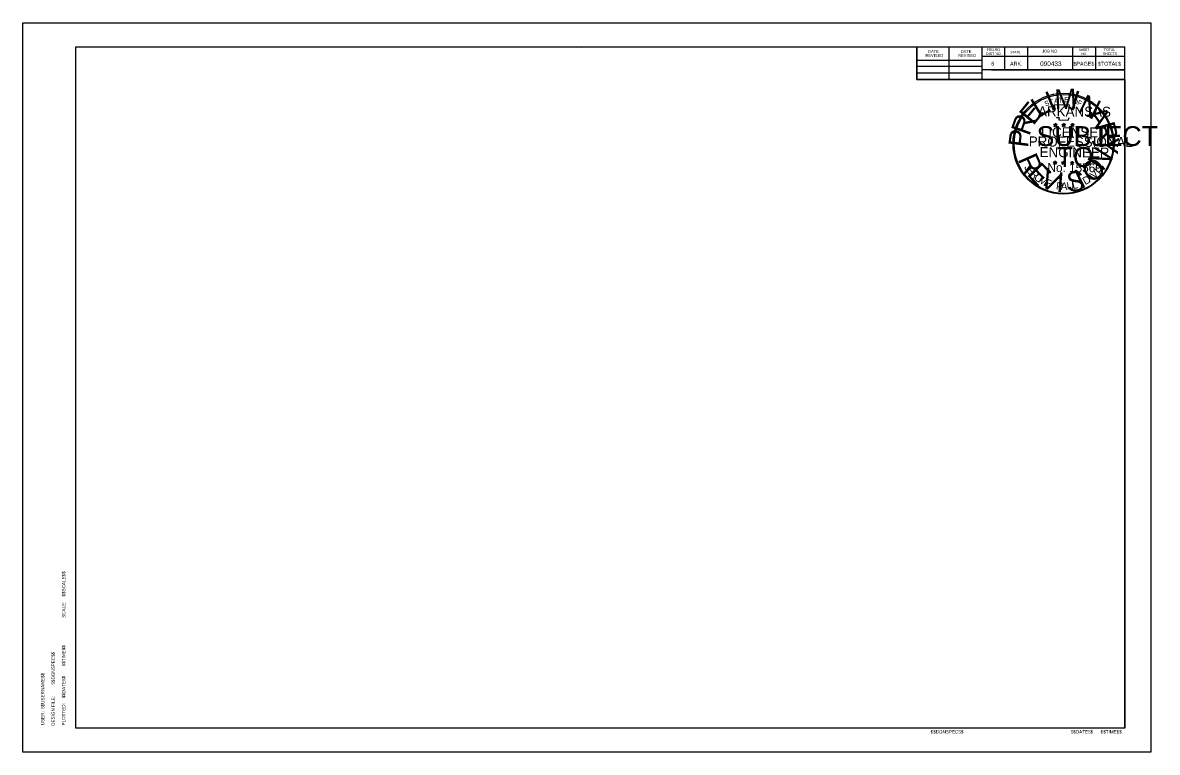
# Model space of a CAD drawing. Extents: x 0 to 34.2, y 0 to 22.
import ezdxf

# ---------------------------------------------------------------- set-up
doc = ezdxf.new("R2010")
doc.units = 0
for name, color, linetype in [('Level 1', 7, 'Continuous'), ('Level 3', 7, 'Continuous'), ('Level 38', 7, 'Continuous'), ('Level 48', 7, 'Continuous'), ('Level 49', 7, 'Continuous'), ('Level 62', 7, 'Continuous'), ('Level 63', 7, 'Continuous'), ('R_Border', 7, 'Continuous'), ('Stamp Mask', 7, 'Continuous')]:
    doc.layers.add(name, color=color, linetype=linetype)

msp = doc.modelspace()

# ---------------------------------------------------------------- linework, layer by layer
at = {"layer": 'Level 1'}
for p, q in [((1.597, 21.272), (33.215, 21.272)), ((1.597, 0.726), (1.597, 21.272)), ((26.951, 20.284), (26.951, 21.272)), ((27.919, 20.284), (27.919, 21.252)), ((28.905, 21.272), (28.905, 20.284)), ((29.589, 21.272), (29.589, 20.578)), ((30.283, 21.272), (30.283, 20.578)), ((31.641, 21.272), (31.641, 20.578)), ((32.335, 21.272), (32.335, 20.578)), ((33.215, 0.726), (33.215, 21.272)), ((26.951, 20.87), (28.905, 20.87)), ((33.215, 20.978), (28.905, 20.978)), ((33.215, 20.98), (33.215, 20.98)), ((26.951, 20.684), (28.905, 20.684)), ((33.215, 20.578), (28.905, 20.578)), ((29.201, 20.578), (33.215, 20.578)), ((26.951, 20.49), (28.905, 20.49)), ((33.215, 20.284), (26.951, 20.284)), ((33.215, 0.726), (1.597, 0.726))]:
    msp.add_line(p, q, dxfattribs=at)
at = {"layer": 'Level 3'}
msp.add_line((16.849, 21.246), (16.849, 21.246), dxfattribs=at)
msp.add_line((16.849, 21.246), (16.849, 21.246), dxfattribs=at)
at = {"layer": 'Level 38'}
msp.add_lwpolyline([(1.597, 0.726), (1.597, 21.272), (26.951, 21.272), (26.951, 20.284), (28.598, 20.284), (28.905, 20.284), (28.905, 20.284), (28.905, 20.284), (33.215, 20.284), (33.215, 19.992), (33.215, 16.66), (33.215, 0.726)], close=True, dxfattribs=at)
at = {"layer": 'Level 49'}
for p, q in [((31.067, 18.933), (31.121, 18.916)), ((31.067, 18.933), (31.107, 18.931)), ((31.067, 18.933), (31.107, 18.929)), ((31.067, 18.933), (31.103, 18.924)), ((31.067, 18.933), (31.103, 18.918)), ((31.067, 18.933), (31.103, 18.916)), ((31.067, 18.933), (31.103, 18.911)), ((31.09, 18.871), (31.121, 18.916)), ((31.09, 18.871), (31.103, 18.914)), ((31.09, 18.871), (31.107, 18.909)), ((31.09, 18.871), (31.108, 18.907)), ((31.09, 18.871), (31.114, 18.903)), ((31.09, 18.871), (31.121, 18.903)), ((31.09, 18.871), (31.121, 18.899)), ((31.121, 18.974), (31.114, 18.933)), ((31.121, 18.974), (31.114, 18.937)), ((31.121, 18.974), (31.118, 18.937)), ((31.121, 18.916), (31.121, 18.974)), ((31.121, 18.974), (31.131, 18.933)), ((31.121, 18.974), (31.129, 18.937)), ((31.121, 18.974), (31.123, 18.937)), ((31.174, 18.933), (31.121, 18.916)), ((31.153, 18.87), (31.121, 18.916)), ((31.153, 18.87), (31.121, 18.903)), ((31.153, 18.87), (31.121, 18.899)), ((31.174, 18.933), (31.125, 18.929)), ((31.153, 18.87), (31.125, 18.903)), ((31.174, 18.933), (31.131, 18.925)), ((31.174, 18.933), (31.131, 18.922)), ((31.153, 18.87), (31.131, 18.914)), ((31.153, 18.87), (31.131, 18.909)), ((31.153, 18.87), (31.136, 18.916)), ((31.174, 18.933), (31.138, 18.922)), ((31.174, 18.933), (31.144, 18.918)), ((31.174, 18.933), (31.146, 18.916)), ((31.319, 18.931), (31.373, 18.916)), ((31.319, 18.931), (31.358, 18.929)), ((31.319, 18.931), (31.358, 18.925)), ((31.319, 18.931), (31.358, 18.924)), ((31.319, 18.931), (31.356, 18.916)), ((31.319, 18.931), (31.356, 18.914)), ((31.319, 18.931), (31.356, 18.909)), ((31.341, 18.87), (31.373, 18.916)), ((31.341, 18.87), (31.358, 18.911)), ((31.341, 18.87), (31.358, 18.909)), ((31.341, 18.87), (31.36, 18.907)), ((31.341, 18.87), (31.365, 18.901)), ((31.341, 18.87), (31.373, 18.901)), ((31.341, 18.87), (31.373, 18.899)), ((31.373, 18.97), (31.365, 18.931)), ((31.373, 18.97), (31.365, 18.933)), ((31.373, 18.97), (31.367, 18.933)), ((31.373, 18.916), (31.373, 18.97)), ((31.373, 18.97), (31.382, 18.931)), ((31.373, 18.97), (31.38, 18.933)), ((31.373, 18.97), (31.375, 18.933)), ((31.425, 18.931), (31.373, 18.916)), ((31.404, 18.87), (31.373, 18.916)), ((31.404, 18.87), (31.373, 18.901)), ((31.404, 18.87), (31.373, 18.899)), ((31.425, 18.931), (31.378, 18.929)), ((31.404, 18.87), (31.378, 18.901)), ((31.425, 18.931), (31.382, 18.924)), ((31.425, 18.931), (31.382, 18.922)), ((31.404, 18.87), (31.382, 18.914)), ((31.404, 18.87), (31.382, 18.907)), ((31.404, 18.87), (31.388, 18.914)), ((31.425, 18.931), (31.389, 18.918)), ((31.425, 18.931), (31.395, 18.916)), ((31.425, 18.931), (31.397, 18.914)), ((31.585, 18.929), (31.639, 18.911)), ((31.585, 18.929), (31.628, 18.924)), ((31.585, 18.929), (31.624, 18.922)), ((31.585, 18.929), (31.624, 18.918)), ((31.585, 18.929), (31.622, 18.914)), ((31.585, 18.929), (31.622, 18.909)), ((31.585, 18.929), (31.622, 18.909)), ((31.605, 18.868), (31.639, 18.911)), ((31.605, 18.868), (31.624, 18.909)), ((31.605, 18.868), (31.628, 18.903)), ((31.605, 18.868), (31.628, 18.901)), ((31.605, 18.868), (31.639, 18.901)), ((31.605, 18.868), (31.635, 18.899)), ((31.605, 18.868), (31.642, 18.894)), ((31.639, 18.966), (31.629, 18.931)), ((31.639, 18.966), (31.635, 18.929)), ((31.639, 18.966), (31.635, 18.929)), ((31.639, 18.911), (31.639, 18.966)), ((31.639, 18.966), (31.65, 18.929)), ((31.639, 18.966), (31.646, 18.929)), ((31.639, 18.966), (31.642, 18.929)), ((31.691, 18.929), (31.639, 18.911)), ((31.669, 18.868), (31.639, 18.911)), ((31.669, 18.868), (31.639, 18.901)), ((31.669, 18.868), (31.639, 18.894)), ((31.691, 18.929), (31.644, 18.924)), ((31.669, 18.868), (31.644, 18.899)), ((31.691, 18.929), (31.65, 18.922)), ((31.691, 18.929), (31.65, 18.916)), ((31.669, 18.868), (31.65, 18.909)), ((31.669, 18.868), (31.65, 18.903)), ((31.669, 18.868), (31.654, 18.909)), ((31.691, 18.929), (31.657, 18.914)), ((31.691, 18.929), (31.659, 18.914)), ((31.691, 18.929), (31.665, 18.911)), ((31.06, 17.79), (31.114, 17.774)), ((31.06, 17.79), (31.099, 17.788)), ((31.06, 17.79), (31.097, 17.783)), ((31.06, 17.79), (31.097, 17.783)), ((31.06, 17.79), (31.097, 17.775)), ((31.06, 17.79), (31.097, 17.774)), ((31.06, 17.79), (31.097, 17.772)), ((31.114, 17.831), (31.103, 17.794)), ((31.114, 17.831), (31.107, 17.79)), ((31.114, 17.831), (31.108, 17.79)), ((31.114, 17.774), (31.114, 17.831)), ((31.114, 17.831), (31.121, 17.79)), ((31.114, 17.831), (31.121, 17.79)), ((31.114, 17.831), (31.114, 17.79)), ((31.166, 17.79), (31.114, 17.774)), ((31.166, 17.79), (31.118, 17.788)), ((31.166, 17.79), (31.121, 17.783)), ((31.166, 17.79), (31.121, 17.781)), ((31.166, 17.79), (31.129, 17.779)), ((31.166, 17.79), (31.133, 17.775)), ((31.166, 17.79), (31.136, 17.774)), ((31.311, 17.79), (31.365, 17.774)), ((31.311, 17.79), (31.35, 17.787)), ((31.311, 17.79), (31.35, 17.783)), ((31.311, 17.79), (31.35, 17.781)), ((31.311, 17.79), (31.348, 17.775)), ((31.311, 17.79), (31.348, 17.772)), ((31.311, 17.79), (31.348, 17.768)), ((31.365, 17.827), (31.356, 17.79)), ((31.365, 17.827), (31.358, 17.79)), ((31.365, 17.827), (31.36, 17.79)), ((31.365, 17.774), (31.365, 17.827)), ((31.365, 17.827), (31.373, 17.788)), ((31.365, 17.827), (31.373, 17.788)), ((31.365, 17.827), (31.365, 17.79)), ((31.415, 17.788), (31.365, 17.774)), ((31.415, 17.788), (31.371, 17.788)), ((31.415, 17.788), (31.373, 17.781)), ((31.415, 17.788), (31.373, 17.781)), ((31.415, 17.788), (31.38, 17.775)), ((31.415, 17.788), (31.386, 17.774)), ((31.415, 17.788), (31.388, 17.772)), ((31.577, 17.787), (31.631, 17.768)), ((31.577, 17.787), (31.616, 17.783)), ((31.577, 17.787), (31.616, 17.779)), ((31.577, 17.787), (31.615, 17.775)), ((31.577, 17.787), (31.615, 17.772)), ((31.577, 17.787), (31.613, 17.768)), ((31.577, 17.787), (31.613, 17.764)), ((31.631, 17.826), (31.622, 17.787)), ((31.631, 17.826), (31.624, 17.787)), ((31.631, 17.826), (31.628, 17.787)), ((31.631, 17.768), (31.631, 17.826)), ((31.631, 17.826), (31.639, 17.787)), ((31.631, 17.826), (31.639, 17.787)), ((31.631, 17.826), (31.631, 17.787)), ((31.683, 17.787), (31.631, 17.768)), ((31.683, 17.787), (31.637, 17.783)), ((31.683, 17.787), (31.639, 17.779)), ((31.683, 17.787), (31.639, 17.775)), ((31.683, 17.787), (31.65, 17.774)), ((31.683, 17.787), (31.652, 17.768)), ((31.683, 17.787), (31.654, 17.768)), ((31.079, 17.733), (31.114, 17.774)), ((31.079, 17.733), (31.097, 17.774)), ((31.079, 17.733), (31.099, 17.766)), ((31.079, 17.733), (31.101, 17.766)), ((31.079, 17.733), (31.114, 17.764)), ((31.079, 17.733), (31.107, 17.76)), ((31.079, 17.733), (31.114, 17.759)), ((31.144, 17.729), (31.11, 17.759)), ((31.144, 17.729), (31.114, 17.774)), ((31.144, 17.729), (31.114, 17.76)), ((31.144, 17.729), (31.116, 17.76)), ((31.144, 17.729), (31.121, 17.774)), ((31.144, 17.729), (31.121, 17.766)), ((31.144, 17.729), (31.129, 17.774)), ((31.33, 17.729), (31.365, 17.774)), ((31.33, 17.729), (31.35, 17.772)), ((31.33, 17.729), (31.35, 17.764)), ((31.33, 17.729), (31.352, 17.764)), ((31.33, 17.729), (31.358, 17.76)), ((31.33, 17.729), (31.365, 17.76)), ((31.33, 17.729), (31.365, 17.757)), ((31.395, 17.729), (31.363, 17.757)), ((31.395, 17.729), (31.365, 17.774)), ((31.395, 17.729), (31.365, 17.76)), ((31.395, 17.729), (31.367, 17.76)), ((31.395, 17.729), (31.373, 17.772)), ((31.395, 17.729), (31.373, 17.766)), ((31.395, 17.729), (31.38, 17.772)), ((31.598, 17.725), (31.631, 17.768)), ((31.598, 17.725), (31.615, 17.768)), ((31.598, 17.725), (31.616, 17.76)), ((31.598, 17.725), (31.62, 17.76)), ((31.598, 17.725), (31.624, 17.757)), ((31.598, 17.725), (31.629, 17.757)), ((31.598, 17.725), (31.631, 17.753)), ((31.661, 17.725), (31.629, 17.757)), ((31.661, 17.725), (31.629, 17.753)), ((31.661, 17.725), (31.631, 17.768)), ((31.661, 17.725), (31.635, 17.757)), ((31.661, 17.725), (31.639, 17.76)), ((31.661, 17.725), (31.642, 17.768)), ((31.661, 17.725), (31.644, 17.768))]:
    msp.add_line(p, q, dxfattribs=at)
for points in [[(31.079, 19.519), (31.116, 19.392)], [(31.607, 19.376), (31.629, 19.42), (31.523, 19.415), (31.548, 19.515), (31.079, 19.519)], [(31.151, 19.152), (31.151, 19.138), (31.235, 19.136), (31.228, 19.067), (31.509, 19.065), (31.538, 19.143)], [(31.121, 18.974), (31.153, 18.87), (31.067, 18.933), (31.174, 18.933), (31.09, 18.871), (31.121, 18.974)], [(31.373, 18.97), (31.404, 18.87), (31.319, 18.931), (31.425, 18.931), (31.341, 18.87), (31.373, 18.97)], [(31.639, 18.966), (31.669, 18.868), (31.585, 18.929), (31.691, 18.929), (31.605, 18.868), (31.639, 18.966)], [(31.114, 17.831), (31.144, 17.729), (31.06, 17.79), (31.166, 17.79), (31.079, 17.733), (31.114, 17.831)], [(31.365, 17.827), (31.395, 17.729), (31.311, 17.79), (31.415, 17.788), (31.33, 17.729), (31.365, 17.827)], [(31.631, 17.826), (31.661, 17.725), (31.577, 17.787), (31.683, 17.787), (31.598, 17.725), (31.631, 17.826)], [(32.329, 17.182), (32.322, 17.206), (32.366, 17.243)], [(32.363, 17.249), (32.37, 17.226), (32.325, 17.187)], [(32.37, 17.23), (32.325, 17.191)], [(32.37, 17.226), (32.327, 17.189)]]:
    msp.add_lwpolyline(points, dxfattribs=at)
for centre, radius in [((31.122, 18.915), 0.026), ((31.122, 18.915), 0.0235), ((31.122, 18.915), 0.0218), ((31.122, 18.915), 0.02), ((31.122, 18.915), 0.0175), ((31.122, 18.915), 0.0162), ((31.122, 18.915), 0.0149), ((31.122, 18.915), 0.0129), ((31.122, 18.915), 0.0113), ((31.122, 18.915), 0.00937), ((31.122, 18.915), 0.00747), ((31.122, 18.915), 0.00557), ((31.122, 18.915), 0.00447), ((31.122, 18.915), 0.00217), ((31.374, 18.913), 0.026), ((31.374, 18.913), 0.0235), ((31.374, 18.913), 0.0218), ((31.374, 18.913), 0.02), ((31.374, 18.913), 0.0175), ((31.374, 18.913), 0.0162), ((31.374, 18.913), 0.0149), ((31.374, 18.913), 0.0129), ((31.374, 18.913), 0.0113), ((31.374, 18.913), 0.00937), ((31.374, 18.913), 0.00747), ((31.374, 18.913), 0.00557), ((31.374, 18.913), 0.00447), ((31.374, 18.913), 0.00217), ((31.64, 18.91), 0.026), ((31.64, 18.91), 0.0235), ((31.64, 18.91), 0.0218), ((31.64, 18.91), 0.02), ((31.64, 18.91), 0.0175), ((31.64, 18.91), 0.0162), ((31.64, 18.91), 0.0149), ((31.64, 18.91), 0.0129), ((31.64, 18.91), 0.0113), ((31.64, 18.91), 0.00937), ((31.64, 18.91), 0.00747), ((31.64, 18.91), 0.00557), ((31.64, 18.91), 0.00447), ((31.64, 18.91), 0.00217), ((31.114, 17.773), 0.026), ((31.114, 17.773), 0.0235), ((31.114, 17.773), 0.0218), ((31.114, 17.773), 0.02), ((31.114, 17.773), 0.0175), ((31.114, 17.773), 0.0162), ((31.114, 17.773), 0.0149), ((31.114, 17.773), 0.0129), ((31.114, 17.773), 0.0113), ((31.114, 17.773), 0.00937), ((31.114, 17.773), 0.00747), ((31.365, 17.772), 0.026), ((31.365, 17.772), 0.0235), ((31.365, 17.772), 0.0218), ((31.365, 17.772), 0.02), ((31.365, 17.772), 0.0175), ((31.365, 17.772), 0.0162), ((31.365, 17.772), 0.0149), ((31.365, 17.772), 0.0129), ((31.365, 17.772), 0.0113), ((31.365, 17.772), 0.00937), ((31.632, 17.768), 0.026), ((31.632, 17.768), 0.0235), ((31.632, 17.768), 0.0218), ((31.632, 17.768), 0.02), ((31.632, 17.768), 0.0175), ((31.632, 17.768), 0.0162), ((31.632, 17.768), 0.0149), ((31.632, 17.768), 0.0129), ((31.114, 17.773), 0.00557), ((31.114, 17.773), 0.00447), ((31.114, 17.773), 0.00217), ((31.365, 17.772), 0.00747), ((31.365, 17.772), 0.00557), ((31.365, 17.772), 0.00447), ((31.365, 17.772), 0.00217), ((31.632, 17.768), 0.0113), ((31.632, 17.768), 0.00937), ((31.632, 17.768), 0.00747), ((31.632, 17.768), 0.00557), ((31.632, 17.768), 0.00447), ((31.632, 17.768), 0.00217)]:
    msp.add_circle(centre, radius, dxfattribs=at)
at = {"layer": 'Level 62'}
msp.add_circle((31.373, 18.34), 1.492, dxfattribs=at)
at = {"layer": 'Level 63'}
msp.add_lwpolyline([(0, 22), (34, 22), (34, 0), (0, 0)], close=True, dxfattribs=at)
at = {"layer": 'Stamp Mask'}
msp.add_circle((31.366, 18.35), 1.521, dxfattribs=at)

# ---------------------------------------------------------------- texts
at = {"layer": 'Level 1'}
for s, height, p in [('FED.RD.', 0.0782, (29.053, 21.144)), ('SHEET', 0.0684, (31.827, 21.144)), ('TOTAL', 0.0782, (32.579, 21.144)), ('REVISED', 0.0879, (27.207, 20.968)), ('DATE', 0.0879, (27.285, 21.086)), ('REVISED', 0.0879, (28.193, 20.968)), ('DATE', 0.0879, (28.271, 21.086)), ('DIST.NO.', 0.0782, (29.033, 21.026)), ('STATE', 0.0684, (29.765, 21.076)), ('JOB NO.', 0.0879, (30.723, 21.096)), ('NO.', 0.0684, (31.905, 21.026)), ('SHEETS', 0.0782, (32.551, 21.026)), ('6', 0.117, (29.189, 20.704)), ('ARK.', 0.1172, (29.755, 20.704)), ('090433', 0.14, (30.662, 20.693)), ('$PAGE$', 0.1172, (31.665, 20.704)), ('$TOTAL$', 0.1172, (32.404, 20.704))]:
    msp.add_text(s, height=height, dxfattribs=at).set_placement(p)
for s, p in [('$$SCALE$$', (1.285, 4.696)), ('SCALE:', (1.285, 4.055)), ('$$TIME$$', (1.282, 2.594)), ('$$DGNSPEC$$', (0.966, 2.041)), ('$$USERNAME$$', (0.654, 1.307)), ('$$DATE$$', (1.282, 1.63)), ('DESIGN FILE:', (0.966, 0.8)), ('PLOTTED:', (1.282, 0.808)), ('USER:', (0.65, 0.816))]:
    msp.add_text(s, height=0.1, rotation=90, dxfattribs=at).set_placement(p)
at = {"layer": 'Level 48'}
for s, p in [('$$DGNSPEC$$', (27.362, 0.568)), ('$$DATE$$', (31.584, 0.568)), ('$$TIME$$', (32.485, 0.568))]:
    msp.add_text(s, height=0.1, dxfattribs=at).set_placement(p)
at = {"layer": 'Level 49'}
for s, height, rotation, p in [('-', 0.241, 13.2326, (31.002, 19.727)), ('-', 0.241, 9.8217, (31.103, 19.752)), ('-', 0.241, 5.4992, (31.214, 19.767)), ('-', 0.241, 359.7886, (31.33, 19.778)), ('-', 0.241, 357.3454, (31.442, 19.774)), ('-', 0.241, 351.7641, (31.551, 19.765)), ('-', 0.241, 346.8073, (31.661, 19.748)), ('-', 0.241, 42.5646, (30.381, 19.372)), ('-', 0.241, 38.5531, (30.448, 19.433)), ('-', 0.241, 35.8341, (30.519, 19.491)), ('-', 0.241, 33.666, (30.606, 19.551)), ('-', 0.241, 28.3942, (30.697, 19.605)), ('-', 0.241, 23.9096, (30.792, 19.651)), ('S', 0.151, 21.1964, (30.827, 19.473)), ('-', 0.241, 18.7785, (30.889, 19.692)), ('T', 0.151, 16.006, (30.965, 19.523)), ('A', 0.151, 10.8156, (31.092, 19.56)), ('T', 0.151, 5.6252, (31.22, 19.584)), ('E', 0.151, 0.4347, (31.386, 19.599)), ('O', 0.151, 350.0539, (31.628, 19.567)), ('F', 0.151, 339.6731, (31.771, 19.53)), ('-', 0.241, 341.9386, (31.756, 19.722)), ('-', 0.241, 337.4575, (31.866, 19.688)), ('-', 0.241, 333.7235, (31.963, 19.649)), ('-', 0.241, 329.2433, (32.048, 19.605)), ('-', 0.241, 325.4651, (32.145, 19.547)), ('-', 0.241, 320.1321, (32.236, 19.484)), ('-', 0.241, 57.673, (30.139, 19.061)), ('-', 0.241, 53.8349, (30.187, 19.143)), ('-', 0.241, 50.2166, (30.251, 19.229)), ('-', 0.241, 48.0254, (30.312, 19.301)), ('ARKANSAS', 0.3015, 359.6024, (30.6, 19.177)), ('-', 0.241, 315.181, (32.327, 19.409)), ('-', 0.241, 309.4821, (32.411, 19.326)), ('-', 0.241, 306.2546, (32.487, 19.234)), ('-', 0.211, 303.2777, (32.562, 19.147)), ('-', 0.241, 71.9969, (30.018, 18.784)), ('-', 0.241, 67.3767, (30.053, 18.879)), ('-', 0.241, 62.4738, (30.092, 18.97)), ('LICENSED', 0.3015, 359.6024, (30.685, 18.552)), ('-', 0.241, 299.2708, (32.608, 19.056)), ('-', 0.241, 294.2652, (32.657, 18.963)), ('-', 0.241, 290.1752, (32.698, 18.879)), ('-', 0.241, 84.7887, (29.955, 18.466)), ('-', 0.241, 80.8037, (29.966, 18.57)), ('-', 0.241, 75.0634, (29.988, 18.676)), ('PROFESSIONAL', 0.30153, 359.6024, (30.319, 18.269)), ('-', 0.241, 284.7257, (32.729, 18.79)), ('-', 0.241, 280.1517, (32.759, 18.676)), ('-', 0.241, 276.1986, (32.785, 18.561)), ('-', 0.241, 93.7983, (29.955, 18.25)), ('-', 0.241, 88.6646, (29.951, 18.36)), ('-', 0.241, 98.5503, (29.966, 18.148)), ('ENGINEER', 0.3015, 359.6024, (30.645, 17.947)), ('-', 0.241, 260.5977, (32.78, 18.159)), ('-', 0.241, 263.1196, (32.793, 18.257)), ('-', 0.241, 273.9325, (32.793, 18.451)), ('-', 0.241, 269.5431, (32.796, 18.358)), ('-', 0.241, 101.3173, (29.983, 18.038)), ('-', 0.241, 105.0602, (30.009, 17.948)), ('-', 0.241, 108.6898, (30.04, 17.855)), ('-', 0.241, 113.6667, (30.077, 17.762)), ('-', 0.241, 247.4911, (32.703, 17.844)), ('-', 0.241, 252.4705, (32.737, 17.947)), ('-', 0.241, 255.365, (32.763, 18.056)), ('-', 0.241, 115.3313, (30.124, 17.669)), ('-', 0.241, 120.0495, (30.176, 17.58)), ('-', 0.241, 125.4958, (30.238, 17.496)), ('J', 0.232, 303.9209, (30.17, 17.634)), ('E', 0.232, 308.618, (30.235, 17.536)), ('R', 0.232, 314.7784, (30.333, 17.418)), ('O', 0.232, 321.6761, (30.456, 17.298)), ('No. 15560', 0.2653, 359.6024, (30.883, 17.5)), ('V', 0.232, 41.4844, (32.289, 17.273)), ('I', 0.232, 49.9999, (32.443, 17.419)), ('S', 0.232, 53.5227, (32.5, 17.486)), ('-', 0.241, 233.4476, (32.543, 17.541)), ('-', 0.241, 238.6736, (32.601, 17.64)), ('-', 0.241, 244.2221, (32.66, 17.751)), ('-', 0.241, 130.3205, (30.305, 17.413)), ('-', 0.241, 133.8262, (30.383, 17.331)), ('-', 0.241, 138.5362, (30.459, 17.26)), ('-', 0.241, 144.2487, (30.546, 17.199)), ('-', 0.241, 147.6922, (30.628, 17.141)), ('M', 0.232, 328.1357, (30.584, 17.2)), ('E', 0.232, 336.4966, (30.764, 17.096)), ('P', 0.232, 351.9783, (31.13, 16.976)), ('A', 0.232, 357.9896, (31.279, 16.957)), ('U', 0.232, 5.7635, (31.472, 16.955)), ('L', 0.232, 13.0992, (31.654, 16.978)), ('D', 0.232, 28.5809, (32.019, 17.1)), ('A', 0.232, 34.8903, (32.156, 17.177)), ('-', 0.241, 215.3387, (32.238, 17.225)), ('-', 0.241, 225.3677, (32.402, 17.372)), ('-', 0.241, 233.4476, (32.472, 17.459)), ('-', 0.241, 151.1728, (30.714, 17.092)), ('-', 0.241, 154.2026, (30.796, 17.053)), ('-', 0.241, 158.1636, (30.889, 17.012)), ('-', 0.241, 162.4007, (30.993, 16.981)), ('-', 0.241, 167.1579, (31.099, 16.957)), ('-', 0.241, 172.7179, (31.214, 16.94)), ('-', 0.241, 176.1207, (31.328, 16.929)), ('-', 0.241, 181.1942, (31.44, 16.932)), ('-', 0.241, 185.4191, (31.562, 16.942)), ('-', 0.241, 190.8882, (31.674, 16.96)), ('-', 0.241, 195.0767, (31.784, 16.99)), ('-', 0.241, 200.3208, (31.886, 17.027)), ('-', 0.241, 203.854, (31.979, 17.068)), ('-', 0.241, 206.9592, (32.074, 17.115)), ('-', 0.241, 211.8515, (32.158, 17.167))]:
    msp.add_text(s, height=height, rotation=rotation, dxfattribs=at).set_placement(p)
at = {"layer": 'Level 62'}
for s, rotation, p in [('I', 22.0105, (30.977, 19.318)), ('M', 2.6943, (31.109, 19.384)), ('I', 343.3781, (31.529, 19.396)), ('E', 50.9849, (30.452, 18.88)), ('L', 31.6686, (30.629, 19.122)), ('N', 333.7199, (31.766, 19.32)), ('R', 70.3011, (30.332, 18.564)), ('A', 304.7456, (32.048, 19.216)), ('R', 285.4294, (32.309, 18.912)), ('P', 82.6089, (30.293, 18.214)), ('Y', 266.1131, (32.444, 18.588)), ('N', 57.1378, (32.558, 17.496)), ('R', 293.7639, (29.981, 17.886)), ('E', 314.3262, (30.239, 17.418)), ('O', 36.5754, (32.195, 17.14)), ('V', 334.8885, (30.611, 17.092)), ('I', 355.4508, (31.139, 16.9)), ('S', 5.732, (31.487, 16.89)), ('I', 26.2943, (31.889, 16.972))]:
    msp.add_text(s, height=0.6, rotation=rotation, dxfattribs=at).set_placement(p)
for s, p in [('SUBJECT', (30.557, 18.28)), ('TO', (31.163, 17.65))]:
    msp.add_text(s, height=0.6, dxfattribs=at).set_placement(p)
at = {"layer": 'R_Border'}
msp.add_text('JOB NO.', height=0.0879, dxfattribs=at).set_placement((30.723, 21.096))

doc.saveas('drawing.dxf')
